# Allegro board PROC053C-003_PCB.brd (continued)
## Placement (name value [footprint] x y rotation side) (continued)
NOREF#226  -  []  106.67 69.55 0 top
NOREF#227  -  []  134.23 67.51 0 top
NOREF#228  -  []  115.71 3.68 90 top
NOREF#229  -  []  169.54 44.35 0 top
NOREF#230  -  []  138.3 47.84 0 top
NOREF#231  -  []  25.4 87.32 90 top
NOREF#232  -  []  139.57 59.14 0 top
NOREF#233  -  []  78.48 33.4 0 top
NOREF#234  -  []  78.48 33.4 90 top
NOREF#235  -  []  65.92 51 90 top
NOREF#236  -  []  8.25 40.97 0 top
NOREF#237  -  []  38.85 125.69 0 top
NOREF#238  -  []  97.04 36.95 90 top
NOREF#239  -  []  90.81 25.78 90 top
NOREF#240  -  []  161.97 70.99 90 top
NOREF#241  -  []  60.57 124.66 90 top
NOREF#242  -  []  103.63 39.76 0 top
NOREF#243  -  []  136.52 67.51 0 top
NOREF#244  -  []  138.04 55.19 90 top
NOREF#245  -  []  97.4 78.94 0 top
NOREF#246  -  []  86.24 67.69 90 top
NOREF#247  -  []  31.49 93.68 0 top
NOREF#248  -  []  28.96 121.23 90 top
NOREF#249  -  []  137.41 132.92 90 top
NOREF#250  -  []  144.01 101.31 0 top
NOREF#251  -  []  143.51 67.51 90 top
NOREF#252  -  []  22.47 134.96 0 top
NOREF#253  -  []  96.24 81.4 0 top
NOREF#254  -  []  78.48 31.24 0 top
NOREF#255  -  []  124.59 28.44 90 top
NOREF#256  -  [unnamed#2]  156.64 72.39 0 top
NOREF#257  -  []  29.6 97.86 90 top
NOREF#258  -  []  92.83 136.36 0 top
NOREF#259  -  []  60.21 63.58 90 top
NOREF#260  -  []  60.7 23.12 0 top
NOREF#261  -  []  28.57 98.39 0 top
NOREF#262  -  []  23.5 133.3 90 top
NOREF#263  -  []  106.9 86.75 0 top
NOREF#264  -  []  141.22 136.48 0 top
NOREF#265  -  []  128.9 30.48 0 top
NOREF#266  -  []  102.15 80.82 90 top
NOREF#267  -  []  120.77 33.9 0 top
NOREF#268  -  []  95.8 76.02 0 top
NOREF#269  -  []  95.88 79.1 0 top
NOREF#270  -  []  90.83 82.5 90 top
NOREF#271  -  []  87.98 82.52 90 top
NOREF#272  -  []  133.84 59.33 90 top
NOREF#273  -  []  95.63 91.02 0 top
NOREF#274  -  []  110.47 86.64 90 top
NOREF#275  -  []  141.6 126.95 0 top
NOREF#276  -  []  161.03 61.05 0 top
NOREF#277  -  []  139.44 130.9 0 top
NOREF#278  -  []  10.79 118.33 0 top
NOREF#279  -  []  25.4 58.37 90 top
NOREF#280  -  []  185.97 62.05 0 top
NOREF#281  -  []  105.53 33.9 0 top
NOREF#282  -  []  106.05 31.87 90 top
NOREF#283  -  []  133.84 44.09 90 top
NOREF#284  -  []  31.49 94.82 90 top
NOREF#285  -  []  58.75 15.21 90 top
NOREF#286  -  []  26.53 50.38 0 top
NOREF#287  -  []  137.29 48.33 90 top
NOREF#288  -  [unnamed#2]  148.59 135.97 0 top
NOREF#289  -  []  93.59 81.4 0 top
NOREF#290  -  []  46.25 103.57 0 top
NOREF#291  -  []  139.95 133.19 0 top
NOREF#292  -  []  76.72 82.88 90 top
NOREF#293  -  []  -15.14 -195.3 0 top
NOREF#294  -  []  75.34 76.65 90 top
NOREF#295  -  []  171.95 23.45 0 top
NOREF#296  -  []  22.34 131.14 90 top
NOREF#297  -  []  138.3 62.56 90 top
NOREF#298  -  []  46.78 103.57 90 top
NOREF#299  -  []  145.92 67.51 0 top
NOREF#300  -  []  175.41 50.28 90 top
NOREF#301  -  []  141.6 58.62 0 top
NOREF#302  -  []  118.87 39.76 0 top
NOREF#303  -  []  154.35 85.09 0 top
NOREF#304  -  []  96.51 32.89 0 top
NOREF#305  -  []  18.28 39.07 90 top
NOREF#306  -  []  111.75 36.95 0 top
NOREF#307  -  []  11.68 31.49 90 top
NOREF#308  -  []  96.4 69.93 90 top
NOREF#309  -  []  90.8 81.27 90 top
NOREF#310  -  []  81.4 81.14 0 top
NOREF#311  -  []  81.8 34.92 90 top
NOREF#312  -  []  160.9 37.54 90 top
NOREF#313  -  []  182.53 98.37 90 top
NOREF#314  -  []  104.79 83.46 0 top
NOREF#315  -  []  103.92 80.82 90 top
NOREF#316  -  []  135.26 52.27 90 top
NOREF#317  -  []  106.16 92.15 90 top
NOREF#318  -  []  170.13 93.43 0 top
NOREF#319  -  []  142.24 60.32 90 top
NOREF#320  -  []  80.77 77.97 0 top
NOREF#321  -  []  103.12 71.45 0 top
NOREF#322  -  []  140.97 132.66 90 top
NOREF#323  -  []  170.93 17.73 0 top
NOREF#324  -  []  29.6 98.88 90 top
NOREF#325  -  []  101.24 73.71 0 top
NOREF#326  -  []  91.71 88.75 90 top
NOREF#327  -  []  174.66 125.68 90 top
NOREF#328  -  []  105.8 137.49 90 top
NOREF#329  -  []  145.92 52.27 0 top
NOREF#330  -  []  157.11 55.58 90 top
NOREF#331  -  []  81.4 82.54 0 top
NOREF#332  -  []  102.88 78.31 90 top
NOREF#333  -  []  108.2 89.32 0 top
NOREF#334  -  []  139.96 67.51 90 top
NOREF#335  -  []  138.56 43.38 90 top
NOREF#336  -  []  154.35 83.96 0 top
NOREF#337  -  []  111.62 27.94 90 top
NOREF#338  -  []  152.65 94.31 90 top
NOREF#339  -  []  114.3 74.81 0 top
NOREF#340  -  []  22.47 133.82 0 top
NOREF#341  -  []  145.04 58.62 90 top
NOREF#342  -  []  104.13 92.15 90 top
NOREF#343  -  []  140.58 52.27 90 top
NOREF#344  -  []  84.71 38.73 90 top
NOREF#345  -  []  48.77 117.55 90 top
NOREF#346  -  []  100.85 78.31 90 top
NOREF#347  -  []  116.96 80.35 0 top
NOREF#348  -  []  24.38 101.44 0 top
NOREF#349  -  []  99.05 80.82 90 top
NOREF#350  -  []  155.92 120.01 90 top
NOREF#351  -  []  101.97 71.45 0 top
NOREF#352  -  []  94.87 125.17 90 top
NOREF#353  -  []  91.71 89.77 0 top
NOREF#354  -  []  100.45 127.45 0 top
NOREF#355  -  []  148.84 70.43 0 top
NOREF#356  -  []  102.15 85.01 90 top
NOREF#357  -  []  172.83 63.58 90 top
NOREF#358  -  []  27.69 31.06 90 top
NOREF#359  -  []  34.15 93.93 90 top
NOREF#360  -  []  34.29 36.39 0 top
NOREF#361  -  []  96.89 126.96 0 top
NOREF#362  -  []  97.28 6.36 0 top
NOREF#363  -  []  104.39 76.94 0 top
NOREF#364  -  []  170.13 92.41 90 top
NOREF#365  -  []  74.32 76.65 0 top
NOREF#366  -  []  98.23 83.17 90 top
NOREF#367  -  []  96.51 36.95 0 top
NOREF#368  -  []  137.55 67.51 90 top
NOREF#369  -  []  29.6 81.1 90 top
NOREF#370  -  []  59.43 40 0 top
NOREF#371  -  []  48.38 24.13 90 top
NOREF#372  -  []  111.75 34.92 0 top
NOREF#373  -  []  23.12 118.94 90 top
NOREF#374  -  []  100.32 78.31 0 top
NOREF#375  -  []  15.24 68.4 90 top
NOREF#376  -  [unnamed#2]  51.46 125.66 0 top
NOREF#377  -  []  80.77 78.99 0 top
NOREF#378  -  []  113.16 137.36 90 top
NOREF#379  -  []  24.91 114.83 0 top
NOREF#380  -  []  175.41 55.36 0 top
NOREF#381  -  []  175.41 50.28 0 top
NOREF#382  -  []  149.61 92.66 90 top
NOREF#383  -  []  31.76 31.06 90 top
NOREF#384  -  []  85.46 36.96 0 top
NOREF#385  -  []  110.48 93.18 0 top
NOREF#386  -  []  25.4 102.05 90 top
NOREF#387  -  []  25.4 84.27 90 top
NOREF#388  -  []  111.62 25.9 0 top
NOREF#389  -  []  29.71 17.41 0 top
NOREF#390  -  []  156.58 55.58 0 top
NOREF#391  -  []  109.35 23.11 90 top
NOREF#392  -  []  105.53 31.87 0 top
NOREF#393  -  []  22.86 117.93 90 top
NOREF#394  -  []  104.13 93.18 0 top
NOREF#395  -  []  169.54 44.35 90 top
NOREF#396  -  []  57.27 37.21 0 top
NOREF#397  -  []  38.85 124.66 90 top
NOREF#398  -  []  108.71 17.52 0 top
NOREF#399  -  []  104.91 76.94 90 top
NOREF#400  -  []  175.4 80.57 90 top
NOREF#401  -  []  96.65 91.51 90 top
NOREF#402  -  []  110.99 31.61 0 top
NOREF#403  -  []  139.69 55.19 0 top
NOREF#404  -  []  90.78 83.87 0 top
NOREF#405  -  []  76.95 115.4 0 top
NOREF#406  -  []  95.75 31.49 0 top
NOREF#407  -  []  173.24 73.86 90 top
NOREF#408  -  []  24.38 60.03 0 top
NOREF#409  -  []  69.22 12.95 90 top
NOREF#410  -  []  101.48 32.38 90 top
NOREF#411  -  []  68.19 12.95 0 top
NOREF#412  -  [unnamed#2]  108.97 42.42 0 top
NOREF#413  -  []  78 55.8 90 top
NOREF#414  -  []  92.83 135.33 90 top
NOREF#415  -  []  25.52 99.26 90 top
NOREF#416  -  []  90.29 85.59 90 top
NOREF#417  -  []  93.72 33.4 0 top
NOREF#418  -  []  18.28 40.09 0 top
NOREF#419  -  []  120.26 137.36 0 top
NOREF#420  -  []  22.74 138.38 90 top
NOREF#421  -  []  80.77 78.99 90 top
NOREF#422  -  []  102.68 82.91 90 top
NOREF#423  -  []  17.66 121.36 90 top
NOREF#424  -  []  138.04 56.22 0 top
NOREF#425  -  []  128.91 23.74 90 top
NOREF#426  -  []  109.44 86.02 0 top
NOREF#427  -  []  139.57 58.62 90 top
NOREF#428  -  []  144.26 122.42 0 top
NOREF#429  -  []  0 0 0 top
NOREF#430  -  []  96.65 90.5 90 top
NOREF#431  -  []  33.78 40.09 0 top
NOREF#432  -  []  105.28 88.85 90 top
NOREF#433  -  []  105.53 28.32 90 top
NOREF#434  -  []  163.95 40.25 0 top
NOREF#435  -  []  175.41 40.12 0 top
NOREF#436  -  []  150.49 57.86 90 top
NOREF#437  -  []  59.94 99.02 0 top
NOREF#438  -  []  139.69 70.43 0 top
NOREF#439  -  []  40.76 121.48 0 top
NOREF#440  -  []  173.54 80.64 90 top
NOREF#441  -  []  75.34 75.64 90 top
NOREF#442  -  []  90.54 72.26 90 top
NOREF#443  -  []  9.28 40.97 90 top
NOREF#444  -  []  100.09 81.85 0 top
NOREF#445  -  []  173.54 78.1 90 top
NOREF#446  -  []  114.17 39.25 0 top
NOREF#447  -  []  25.52 57.24 0 top
NOREF#448  -  [unnamed#3]  185.42 147.32 0 top
NOREF#449  -  []  96.67 88.61 90 top
NOREF#450  -  []  129.04 29.07 90 top
NOREF#451  -  []  36.31 22.86 0 top
NOREF#452  -  []  120.77 25.78 0 top
NOREF#453  -  []  179.32 54.43 90 top
NOREF#454  -  []  29.6 55.32 90 top
NOREF#455  -  []  109.83 77.72 90 top
NOREF#456  -  []  144.01 100.78 90 top
NOREF#457  -  []  186.71 96.47 90 top
NOREF#458  -  []  87.96 83.82 0 top
NOREF#459  -  []  53.71 24.13 90 top
NOREF#460  -  []  146.05 58.62 0 top
NOREF#461  -  []  102.15 82.91 0 top
NOREF#462  -  []  122.42 19.93 0 top
NOREF#463  -  [unnamed#2]  27.56 61.8 0 top
NOREF#464  -  []  100.98 86.31 90 top
NOREF#465  -  []  149.47 97.49 0 top
NOREF#466  -  []  93.72 31.24 90 top
NOREF#467  -  []  37.61 100.17 90 top
NOREF#468  -  []  140.58 52.79 0 top
NOREF#469  -  []  100.45 128.47 0 top
NOREF#470  -  []  142.24 60.84 0 top
NOREF#471  -  []  90.29 31.87 90 top
NOREF#472  -  []  85.21 34.17 0 top
NOREF#473  -  [unnamed#2]  36.2 75.65 0 top
NOREF#474  -  []  175.41 45.2 90 top
NOREF#475  -  []  94.76 77.62 90 top
NOREF#476  -  []  94.81 71.1 0 top
NOREF#477  -  []  97.91 86.28 90 top
NOREF#478  -  []  25.4 105.1 90 top
NOREF#479  -  []  97.37 76.02 90 top
NOREF#480  -  []  -29.48 8.76 90 top
NOREF#481  -  []  135.12 58.62 90 top
NOREF#482  -  []  143.51 52.27 90 top
NOREF#483  -  []  88.13 81.4 90 top
NOREF#484  -  []  94.76 78.65 0 top
NOREF#485  -  []  102.8 73.71 90 top
NOREF#486  -  []  101.48 130.5 90 top
NOREF#487  -  []  93.72 33.4 90 top
NOREF#488  -  []  37.61 100.17 0 top
NOREF#489  -  []  103.39 80.82 0 top
NOREF#490  -  []  56.13 94.95 0 top
NOREF#491  -  []  20.7 120.09 90 top
NOREF#492  -  []  60.57 125.69 0 top
NOREF#493  -  []  112.15 25.9 90 top
NOREF#494  -  []  147.07 58.62 90 top
NOREF#495  -  []  42.03 91.64 90 top
NOREF#496  -  []  172.71 74.89 0 top
NOREF#497  -  []  132.46 127.1 90 top
NOREF#498  -  []  182.52 17.4 0 top
NOREF#499  -  []  28.57 56.86 0 top
NOREF#500  -  []  106.77 76.28 0 top
NOREF#501  -  []  100.33 83.18 90 top
NOREF#502  -  []  102.5 71.45 90 top
NOREF#503  -  []  47.75 118.07 0 top
NOREF#504  -  []  102.15 86.04 0 top
NOREF#505  -  []  81.4 81.14 90 top
NOREF#506  -  []  44.57 141.94 0 top
NOREF#507  -  []  150.49 67 90 top
NOREF#508  -  []  66.67 40 90 top
NOREF#509  -  []  150.49 58.38 0 top
NOREF#510  -  []  167.68 70.99 0 top
NOREF#511  -  []  109.47 84.97 0 top
NOREF#512  -  []  90.78 83.87 90 top
NOREF#513  -  []  31.49 77.04 0 top
NOREF#514  -  []  109.72 72.4 0 top
NOREF#515  -  []  103.64 71.45 90 top
NOREF#516  -  []  105.16 70.94 90 top
NOREF#517  -  []  90.83 82.5 0 top
NOREF#518  -  []  137.54 43.38 0 top
NOREF#519  -  []  97.22 38.88 0 top
NOREF#520  -  []  101.34 78.31 0 top
NOREF#521  -  [unnamed#3]  185.42 5.08 0 top
NOREF#522  -  []  109.44 87.16 0 top
NOREF#523  -  [unnamed#2]  78.74 41.78 0 top
NOREF#524  -  []  105.41 72.97 0 top
NOREF#525  -  []  98.65 73.71 90 top
NOREF#526  -  []  38.87 108.41 90 top
NOREF#527  -  []  24.38 84.8 0 top
NOREF#528  -  []  104.66 73.74 90 top
NOREF#529  -  [unnamed#2]  181.25 143.85 0 top
NOREF#530  -  []  81.27 32.89 0 top
NOREF#531  -  []  134.99 47.57 90 top
NOREF#532  -  []  29.6 80.08 90 top
NOREF#533  -  []  116.2 32.38 0 top
NOREF#534  -  []  135.25 63.57 90 top
NOREF#535  -  []  93.01 72.69 90 top
NOREF#536  -  []  108.53 80.3 0 top
NOREF#537  -  []  58.75 15.74 0 top
NOREF#538  -  []  147.06 96.21 0 top
NOREF#539  -  []  40.89 120.35 0 top
NOREF#540  -  []  155.95 75.53 0 top
NOREF#541  -  []  93.09 28.69 0 top
NOREF#542  -  []  90.29 33.9 0 top
NOREF#543  -  []  103.12 88.72 90 top
NOREF#544  -  []  97.42 125.93 90 top
NOREF#545  -  []  109.35 28.44 90 top
NOREF#546  -  []  46.25 102.56 0 top
NOREF#547  -  []  171.44 68.16 0 top
NOREF#548  -  []  78.48 31.24 90 top
NOREF#549  -  []  139.57 43.9 0 top
NOREF#550  -  []  98.69 72.51 0 top
NOREF#551  -  []  163.2 40.25 90 top
NOREF#552  -  []  154.87 82.93 90 top
NOREF#553  -  []  66.67 76.03 0 top
NOREF#554  -  []  186.49 62.05 90 top
NOREF#555  -  []  102.1 89.75 0 top
NOREF#556  -  []  166.92 88.27 90 top
NOREF#557  -  []  110.48 92.15 90 top
NOREF#558  -  [unnamed#2]  27.69 104.35 0 top
NOREF#559  -  []  96.67 89.64 0 top
NOREF#560  -  []  60.44 40 90 top
NOREF#561  -  []  117.99 78.81 90 top
NOREF#562  -  []  93.85 79.49 90 top
NOREF#563  -  []  140.07 135.46 0 top
NOREF#564  -  []  24.38 87.85 0 top
NOREF#565  -  []  111.89 75.61 90 top
NOREF#566  -  []  44.06 135.85 0 top
NOREF#567  -  []  90.29 28.32 90 top
NOREF#568  -  []  149.36 70.43 90 top
NOREF#569  -  []  98.42 124.67 0 top
NOREF#570  -  []  167.94 89.29 0 top
NOREF#571  -  []  99.95 38.73 90 top
NOREF#572  -  []  175.41 47.74 90 top
NOREF#573  -  []  106.05 33.9 90 top
NOREF#574  -  []  96.33 76.02 90 top
NOREF#575  -  []  174.4 5.21 90 top
NOREF#576  -  []  135.26 67.51 90 top
NOREF#577  -  []  143.51 68.03 0 top
NOREF#578  -  []  101.46 67.39 0 top
NOREF#579  -  []  53.97 94.95 0 top
NOREF#580  -  []  95.75 31.49 90 top
NOREF#581  -  []  107.93 86.23 90 top
NOREF#582  -  []  96.24 81.4 90 top
NOREF#583  -  []  94.11 28.69 90 top
NOREF#584  -  []  80.77 77.97 90 top
NOREF#585  -  []  143.51 52.79 0 top
NOREF#586  -  []  174.13 126.7 0 top
NOREF#587  -  []  28.44 121.23 0 top
NOREF#588  -  []  23.87 35.78 0 top
NOREF#589  -  []  67.19 75.01 90 top
NOREF#590  -  []  18.79 72.48 0 top
NOREF#591  -  []  95.88 78.08 90 top
NOREF#592  -  []  116.72 32.38 90 top
NOREF#593  -  []  142.25 70.43 90 top
NOREF#594  -  []  64.89 51 0 top
NOREF#595  -  []  105.53 29.34 0 top
NOREF#596  -  []  140.71 130.76 0 top
NOREF#597  -  []  81.98 38.88 0 top
NOREF#598  -  [unnamed#2]  36.96 51.26 0 top
NOREF#599  -  [unnamed#2]  93.6 22.61 0 top
NOREF#600  -  []  135.12 59.14 0 top
NOREF#601  -  []  98.01 80.7 0 top
NOREF#602  -  []  133.47 45.03 0 top
NOREF#603  -  []  102.15 81.85 0 top
NOREF#604  -  []  98.12 73.71 0 top
NOREF#605  -  []  98.94 123.65 90 top
NOREF#606  -  []  22.86 118.45 0 top
NOREF#607  -  []  103.45 86.03 0 top
NOREF#608  -  []  17.65 138.38 0 top
NOREF#609  -  []  105.28 87.83 90 top
NOREF#610  -  []  104.26 12.57 0 top
NOREF#611  -  []  104.77 137.49 0 top
NOREF#612  -  []  63.5 121.36 90 top
NOREF#613  -  []  150.49 68.54 0 top
NOREF#614  -  []  60.06 108.41 0 top
NOREF#615  -  []  101.53 76.7 90 top
NOREF#616  -  [unnamed#3]  5.08 5.08 0 top
NOREF#617  -  []  93.09 73.96 0 top
NOREF#618  -  []  102.61 67.39 0 top
NOREF#619  -  []  161.97 70.99 0 top
NOREF#620  -  []  190.5 0 90 top
NOREF#621  -  []  49.65 121.99 90 top
NOREF#622  -  []  24.38 63.08 0 top
NOREF#623  -  []  24.38 105.63 0 top
NOREF#624  -  []  11.68 32.52 0 top
NOREF#625  -  []  115.32 75.3 90 top
NOREF#626  -  []  101.48 129.49 90 top
NOREF#627  -  []  147.06 97.23 0 top
NOREF#628  -  []  44.06 134.82 90 top
NOREF#629  -  []  149.09 93.68 0 top
NOREF#630  -  []  175.41 42.66 0 top
NOREF#631  -  []  76.19 80.85 0 top
NOREF#632  -  []  137.55 52.27 90 top
NOREF#633  -  []  96.84 76.02 0 top
NOREF#634  -  []  15.24 93.16 0 top
NOREF#635  -  []  155.74 102.96 0 top
NOREF#636  -  []  162.68 40.25 0 top
NOREF#637  -  []  152.19 28.25 0 top
NOREF#638  -  []  107.1 89.32 0 top
NOREF#639  -  [unnamed#2]  174.16 14.76 90 top
NOREF#640  -  []  95.33 71.1 90 top
NOREF#641  -  []  135.12 43.9 0 top
NOREF#642  -  []  48.87 91.51 0 top
NOREF#643  -  []  139.57 43.38 90 top
NOREF#644  -  []  116.96 79.34 0 top
NOREF#645  -  []  34.79 77.04 0 top
NOREF#646  -  []  156.98 75 90 top
NOREF#647  -  []  31.49 52.27 0 top
NOREF#648  -  [unnamed#2]  35.94 95.97 0 top
NOREF#649  -  []  96.51 28.19 90 top
NOREF#650  -  []  165.78 79.24 90 top
NOREF#651  -  []  136.5 129.13 0 top
NOREF#652  -  []  174.87 80.57 0 top
NOREF#653  -  []  106.03 76.99 90 top
NOREF#654  -  []  138.3 48.86 0 top
NOREF#655  -  []  77.99 88.64 90 top
NOREF#656  -  []  129.16 46.6 90 top
NOREF#657  -  []  96.11 86.03 90 top
NOREF#658  -  []  144.79 122.42 90 top
NOREF#659  -  []  99.31 83.7 0 top
NOREF#660  -  []  156.27 102.96 90 top
NOREF#661  -  []  107.1 88.29 90 top
NOREF#662  -  []  11.82 117.8 90 top
NOREF#663  -  []  109.42 83.86 0 top
NOREF#664  -  []  28.57 81.62 0 top
NOREF#665  -  []  98.95 86.28 90 top
NOREF#666  -  []  28.57 55.84 0 top
NOREF#667  -  []  103.45 86.03 90 top
NOREF#668  -  []  90.29 25.78 0 top
NOREF#669  -  []  120.77 28.32 90 top
NOREF#670  -  []  34.8 39.57 90 top
NOREF#671  -  []  25.52 81.48 90 top
NOREF#672  -  []  98.95 87.31 0 top
NOREF#673  -  []  161.22 82.8 90 top
NOREF#674  -  []  109.83 76.7 90 top
NOREF#675  -  []  119.76 82 0 top
NOREF#676  -  []  100.5 77.23 0 top
NOREF#677  -  []  111.75 79.2 0 top
NOREF#678  -  []  88.39 39.76 0 top
NOREF#679  -  []  48.38 24.13 0 top
NOREF#680  -  []  106.16 93.18 0 top
NOREF#681  -  []  77.46 86.44 0 top
NOREF#682  -  []  28.57 99.4 0 top
NOREF#683  -  []  95.63 93.05 0 top
NOREF#684  -  []  155.31 24.98 0 top
NOREF#685  -  []  112.26 21.08 0 top
NOREF#686  -  []  24.38 61.05 0 top
NOREF#687  -  []  85.21 33.14 90 top
NOREF#688  -  []  100.19 73.71 0 top
NOREF#689  -  []  101.11 80.82 90 top
NOREF#690  -  []  171.95 22.43 90 top
NOREF#691  -  []  107.2 69.55 90 top
NOREF#692  -  []  105.41 81.04 0 top
NOREF#693  -  []  34.79 52.27 90 top
NOREF#694  -  []  152.65 94.83 0 top
NOREF#695  -  []  49.65 118.33 0 top
NOREF#696  -  []  102.8 75.74 90 top
NOREF#697  -  []  90.29 29.34 0 top
NOREF#698  -  []  132.46 127.1 0 top
NOREF#699  -  []  167.25 46.65 0 top
NOREF#700  -  []  27.17 31.06 0 top
NOREF#701  -  []  86.22 34.17 0 top
NOREF#702  -  []  95.88 69.93 0 top
NOREF#703  -  []  101.11 81.85 0 top
NOREF#704  -  []  97.4 78.94 90 top
NOREF#705  -  []  15.24 68.4 0 top
NOREF#706  -  []  95.63 92.04 0 top
NOREF#707  -  [unnamed#2]  5.08 10.79 0 top
NOREF#708  -  []  33.78 39.08 0 top
NOREF#709  -  []  31.49 77.04 90 top
NOREF#710  -  []  151.63 97.61 0 top
NOREF#711  -  []  86.22 33.14 90 top
NOREF#712  -  []  88.13 81.4 0 top
NOREF#713  -  []  159.94 89.29 0 top
NOREF#714  -  []  152.82 105.63 0 top
NOREF#715  -  []  90.71 88.72 90 top
NOREF#716  -  []  93.72 31.24 0 top
NOREF#717  -  []  103.89 78.31 90 top
NOREF#718  -  []  25.52 99.78 0 top
NOREF#719  -  []  96.27 73.39 0 top
NOREF#720  -  []  91.69 72.26 90 top
NOREF#721  -  []  121.29 31.87 90 top
NOREF#722  -  []  108.32 92.15 90 top
NOREF#723  -  []  95.7 84.65 90 top
NOREF#724  -  []  66.3 140.67 90 top
NOREF#725  -  []  102.28 75.74 0 top
NOREF#726  -  []  83.69 39.25 0 top
NOREF#727  -  []  69.59 139.14 90 top
NOREF#728  -  []  -17.13 -248.13 90 top
NOREF#729  -  []  99.05 81.85 0 top
NOREF#730  -  []  115.06 73.5 0 top
NOREF#731  -  []  104.13 73.74 0 top
NOREF#732  -  []  128.78 24.5 90 top
NOREF#733  -  []  108.96 31.24 90 top
NOREF#734  -  []  105.53 25.78 0 top
NOREF#735  -  []  93.85 79.49 0 top
NOREF#736  -  []  96.39 128.98 90 top
NOREF#737  -  []  134.99 47.57 0 top
NOREF#738  -  []  25.4 100.91 90 top
NOREF#739  -  []  171.44 67.13 90 top
NOREF#740  -  []  24.38 85.81 0 top
NOREF#741  -  []  105.41 72.97 90 top
NOREF#742  -  []  25.52 82 0 top
NOREF#743  -  []  108.96 31.24 0 top
NOREF#744  -  []  108.33 23.11 0 top
NOREF#745  -  []  139.44 129.87 90 top
NOREF#746  -  []  23.87 35.25 90 top
NOREF#747  -  []  167.25 45.62 90 top
NOREF#748  -  []  36.84 22.86 90 top
NOREF#749  -  []  175.41 40.12 90 top
NOREF#750  -  []  95.7 84.65 0 top
NOREF#751  -  []  177.69 17.4 0 top
NOREF#752  -  []  140.07 135.46 90 top
NOREF#753  -  []  102.23 13.34 0 top
NOREF#754  -  []  45.09 141.94 90 top
NOREF#755  -  []  175.41 57.9 0 top
NOREF#756  -  []  142.63 58.62 90 top
NOREF#757  -  []  4.95 33.03 0 top
NOREF#758  -  []  68.19 106.12 90 top
NOREF#759  -  []  175.41 42.66 90 top
NOREF#760  -  []  142.12 126.95 90 top
NOREF#761  -  []  41.79 121.48 90 top
NOREF#762  -  []  87.96 83.82 90 top
NOREF#763  -  []  105.28 89.86 90 top
NOREF#764  -  []  135.25 64.1 0 top
NOREF#765  -  []  99.72 71.99 90 top
NOREF#766  -  []  165.48 53.29 90 top
NOREF#767  -  []  133.47 60.27 90 top
NOREF#768  -  [unnamed#3]  5.08 147.32 0 top
NOREF#769  -  []  104.26 12.57 90 top
NOREF#770  -  []  23.5 134.44 90 top
NOREF#771  -  []  138.3 47.32 90 top
NOREF#772  -  []  66.67 40 0 top
NOREF#773  -  []  136.5 129.13 90 top
NOREF#774  -  []  81.8 32.89 90 top
NOREF#775  -  []  168.83 81.15 0 top
NOREF#776  -  []  103.13 67.39 90 top
NOREF#777  -  []  17.14 121.36 0 top
NOREF#778  -  []  151.63 97.61 90 top
NOREF#779  -  []  41.41 120.35 90 top
NOREF#780  -  []  110.49 84.45 90 top
NOREF#781  -  []  155.92 120.01 0 top
NOREF#782  -  []  112.46 38.88 0 top
NOREF#783  -  []  148.09 96.21 90 top
NOREF#784  -  []  161.54 50.67 90 top
NOREF#785  -  []  152.65 95.97 0 top
NOREF#786  -  []  102.28 73.71 0 top
NOREF#787  -  []  173.87 5.21 0 top
NOREF#788  -  []  120.77 36.44 90 top
NOREF#789  -  []  160.7 82.8 0 top
NOREF#790  -  []  123.57 28.44 0 top
NOREF#791  -  []  38.35 108.41 0 top
NOREF#792  -  []  31.49 92.66 90 top
NOREF#793  -  []  57.27 37.21 90 top
NOREF#794  -  []  129.42 30.48 90 top
NOREF#795  -  []  137.41 133.94 0 top
NOREF#796  -  []  136.52 52.27 0 top
NOREF#797  -  []  115.32 74.29 90 top
NOREF#798  -  []  105.32 83.46 90 top
NOREF#799  -  []  25.43 114.83 90 top
NOREF#800  -  []  101.11 84.21 0 top
NOREF#801  -  []  96.39 129.5 0 top
NOREF#802  -  []  -17.13 -99.99 0 top
NOREF#803  -  []  77.46 89.67 0 top
NOREF#804  -  []  60.46 100.03 90 top
NOREF#805  -  []  150.38 70.43 90 top
NOREF#806  -  []  101.08 89.75 0 top
NOREF#807  -  []  172.31 63.58 0 top
NOREF#808  -  []  172.71 68.5 0 top
NOREF#809  -  []  60.7 22.6 90 top
NOREF#810  -  []  135.12 43.38 90 top
NOREF#811  -  []  96.38 25.78 0 top
NOREF#812  -  [unnamed#2]  41.1 114.74 0 top
NOREF#813  -  []  24.38 102.58 0 top
NOREF#814  -  []  56.49 43.92 0 top
NOREF#815  -  []  85.72 67.69 0 top
NOREF#816  -  []  157.62 108.97 90 top
NOREF#817  -  []  109.55 79.78 90 top
NOREF#818  -  []  120.77 37.47 0 top
NOREF#819  -  []  170.93 24.85 0 top
NOREF#820  -  []  120.77 31.87 0 top
NOREF#821  -  []  110.44 83.33 90 top
NOREF#822  -  []  175.41 52.82 90 top
NOREF#823  -  []  93.85 125.17 0 top
NOREF#824  -  []  24.38 103.59 0 top
NOREF#825  -  []  97.28 5.83 90 top
NOREF#826  -  []  25.4 59.51 90 top
NOREF#827  -  []  97.2 83.69 0 top
NOREF#828  -  []  137.54 58.62 0 top
NOREF#829  -  []  102.23 12.31 90 top
NOREF#830  -  []  24.26 122.88 90 top
NOREF#831  -  []  93.85 128.98 90 top
NOREF#832  -  []  142.24 123.77 0 top
NOREF#833  -  []  119.89 39.23 90 top
NOREF#834  -  []  65.65 40 90 top
NOREF#835  -  []  76.95 114.38 90 top
NOREF#836  -  []  24.38 83.66 0 top
NOREF#837  -  []  106.8 83.36 0 top
NOREF#838  -  []  156.58 57.86 90 top
NOREF#839  -  []  105.41 73.99 0 top
NOREF#840  -  []  96.51 29.21 0 top
NOREF#841  -  []  101.99 67.39 90 top
NOREF#842  -  [unnamed#2]  87.38 66.88 0 top
NOREF#843  -  []  53.71 89.01 90 top
NOREF#844  -  []  101.86 78.31 90 top
NOREF#845  -  []  100.96 32.38 0 top
NOREF#846  -  []  175.41 57.9 90 top
NOREF#847  -  []  105.53 36.44 90 top
NOREF#848  -  []  97.91 87.31 0 top
NOREF#849  -  []  42.03 91.64 0 top
NOREF#850  -  []  63.13 120.35 90 top
NOREF#851  -  []  108.77 78.74 90 top
NOREF#852  -  []  90.71 89.75 0 top
NOREF#853  -  []  107.32 83.36 90 top
NOREF#854  -  []  108.96 33.4 90 top
NOREF#855  -  []  165.48 53.29 0 top
NOREF#856  -  []  136.27 48.33 0 top
NOREF#857  -  []  59.68 63.58 0 top
NOREF#858  -  []  107.74 79.26 0 top
NOREF#859  -  []  112.28 36.95 90 top
NOREF#860  -  []  112.77 78.68 90 top
NOREF#861  -  []  59.94 97.99 90 top
NOREF#862  -  []  110.47 85.49 90 top
NOREF#863  -  []  160.61 79.89 0 top
NOREF#864  -  []  128.01 27.19 0 top
NOREF#865  -  []  152.62 113.97 0 top
NOREF#866  -  []  57.12 89.05 90 top
NOREF#867  -  []  77.46 86.44 90 top
NOREF#868  -  []  140.22 70.43 90 top
NOREF#869  -  []  102.1 88.72 90 top
NOREF#870  -  [unnamed#2]  184.18 8.89 0 top
NOREF#871  -  []  175.41 55.36 90 top
NOREF#872  -  []  140.71 56.22 0 top
NOREF#873  -  [unnamed#2]  27.94 86.82 0 top
NOREF#874  -  []  41.14 101.05 0 top
NOREF#875  -  []  144.01 58.62 0 top
NOREF#876  -  []  156.58 58.89 0 top
NOREF#877  -  []  101.76 73.71 90 top
NOREF#878  -  []  155.11 78.63 0 top
NOREF#879  -  []  90.29 37.47 0 top
NOREF#880  -  []  29.6 56.33 90 top
NOREF#881  -  []  107.93 85.19 90 top
NOREF#882  -  []  128.01 29.6 0 top
NOREF#883  -  []  105.41 73.99 90 top
NOREF#884  -  []  15.24 93.16 90 top
NOREF#885  -  []  108.2 88.29 90 top
NOREF#886  -  []  162.04 37.54 90 top
NOREF#887  -  []  140.71 70.43 90 top
NOREF#888  -  []  97.82 148.45 0 top
NOREF#889  -  []  35.31 36.39 90 top
NOREF#890  -  []  60.44 40 0 top
NOREF#891  -  []  94.1 85.56 0 top
NOREF#892  -  []  56.65 94.95 90 top
NOREF#893  -  []  106.43 80.51 90 top
NOREF#894  -  []  170.93 23.83 90 top
NOREF#895  -  []  53.71 24.13 0 top
NOREF#896  -  []  121.29 25.78 90 top
NOREF#897  -  []  98.43 77.82 90 top
NOREF#898  -  []  120.77 29.34 0 top
NOREF#899  -  []  37.33 22.86 0 top
NOREF#900  -  []  179.32 54.43 0 top
NOREF#901  -  []  31.23 31.06 0 top
NOREF#902  -  [unnamed#2]  117.22 96.98 0 top
NOREF#903  -  []  150.11 100.78 0 top
NOREF#904  -  []  108.32 93.18 0 top
NOREF#905  -  []  138.93 67.51 0 top
NOREF#906  -  [unnamed#2]  130.94 70.69 0 bottom
NOREF#907  -  [unnamed#2]  156.84 89.49 0 bottom
NOREF#908  -  [unnamed#2]  131.06 40.72 0 bottom
NOREF#909  -  [unnamed#2]  181.25 143.85 180 bottom
NOREF#910  -  [unnamed#2]  4.45 142.96 180 bottom
NOREF#911  -  [unnamed#2]  86.49 118.06 180 bottom
NOREF#912  -  [unnamed#2]  33.66 32.59 270 bottom
NOREF#913  -  [unnamed#2]  188.09 63.33 0 bottom
NOREF#914  -  [unnamed#2]  26.16 123.02 270 bottom
NOREF#915  -  [unnamed#2]  104.77 135.21 180 bottom
NOREF#916  -  [unnamed#2]  151.89 55.71 0 bottom
NOREF#917  -  [unnamed#2]  184.18 8.89 180 bottom
NOREF#918  -  [unnamed#2]  25.91 40.47 270 bottom
NOREF#919  -  [unnamed#2]  5.08 10.79 180 bottom
NOREF#920  -  [unnamed#2]  144.15 102.32 0 bottom
Q1  BSS138  [SOT23-3]  12.45 3.76 90 bottom
Q2  BSS138  [SOT23-3]  19.05 3.76 90 bottom
Q3  BSS138  [SOT23-3]  12.45 10.37 90 bottom
Q4  BSS138  [SOT23-3]  19.05 10.37 90 bottom
Q5  BSS138  [SOT23-3]  12.45 7.07 90 bottom
Q6  BSS138  [SOT23-3]  19.05 7.07 90 bottom
Q7  NTF6P02T3G  [SOT223]  45.59 112.6 0 bottom
Q8  NTF6P02T3G  [SOT223]  67.44 111.84 0 top
Q9  BSS138  [SOT23-3]  74.3 148.54 90 top
Q10  BSS138  [SOT23-3]  12.45 20.53 90 bottom
Q11  BSS138  [SOT23-3]  12.45 13.92 90 bottom
Q12  BSS138  [SOT23-3]  19.05 17.23 90 bottom
Q13  BSS138  [SOT23-3]  19.05 13.92 90 bottom
Q14  BSS138  [SOT23-3]  19.05 20.66 90 bottom
Q15  BSS138  [SOT23-3]  12.45 17.23 90 bottom
Q16  BSS138  [SOT23-3]  143.13 13.84 0 top
Q20  BSS138  [SOT23-3]  79.98 103.22 180 bottom
Q21  BSS138  [SOT23-3]  76.55 103.22 180 bottom
Q22  BSS138  [SOT23-3]  73.12 103.22 180 bottom
Q23  BSS138  [SOT23-3]  69.85 94.06 180 bottom
Q24  BSS138  [SOT23-3]  69.72 86.95 180 bottom
Q25  BSS138  [SOT23-3]  69.34 101.17 180 bottom
Q26  MMBT2907A  [SOT23-3-44M]  38.86 97.16 90 bottom
Q27  MMBT2907A  [SOT23-3-44M]  113.41 128.27 180 bottom
R1_1  0  [SM-7351-RES-0603]  179.31 7.63 90 top
R2  10K  [SM-7351-RES-0402]  127.89 64.85 0 top
R2_1  10K  [SM-7351-RES-0402]  172.7 6.49 180 top
R3  22.1  [SM-7351-RES-0402]  182.02 96.6 0 bottom
R4  1M  [SM-7351-RES-0402]  77.6 82.38 270 top
R5  0  [SM-7351-RES-0402]  79.25 82.76 180 top
R6  0  [SM-7351-RES-0402]  133.73 74.07 0 top
R7  0  [SM-7351-RES-0402]  124.08 65.49 0 top
R8  0  [SM-7351-RES-0402]  124.08 69.3 0 top
R9  0  [SM-7351-RES-0402]  136.91 126.45 180 bottom
R10  10K  [SM-7351-RES-0402]  170.05 45.76 180 bottom
R11  100  [SM-7351-RES-0402]  168.15 53.55 0 bottom
R13  0  [SM-7351-RES-0402]  69.74 82.33 180 top
R14  0  [SM-7351-RES-0402]  130.43 114.76 270 top
R15  0  [SM-7351-RES-0402]  132.72 114.76 270 top
R16  1K  [SM-7351-RES-0402]  134.49 122.38 180 bottom
R17  1K  [SM-7351-RES-0402]  137.13 122.3 180 bottom
R18  10K  [SM-7351-RES-0402]  144.54 126.96 90 bottom
R19  0  [SM-7351-RES-0402]  142.49 140.54 90 top
R20  0  [SM-7351-RES-0402]  142.88 135.97 90 top
R21  1K  [SM-7351-RES-0402]  138.94 128.35 270 bottom
R22  10K  [SM-7351-RES-0402]  89.79 108.79 270 top
R23  0  [SM-7351-RES-0402]  101.85 112.48 270 top
R24  0  [SM-7351-RES-0402]  101.98 99.78 270 top
R25  0  [SM-7351-RES-0402]  98.68 108.79 270 top
R26  0  [SM-7351-RES-0402]  91.06 124.16 90 top
R27  0  [SM-7351-RES-0402]  91.06 108.79 270 top
R28  0  [SM-7351-RES-0402]  101.35 124.16 90 top
R29  0  [SM-7351-RES-0402]  97.41 124.16 90 top
R30  0  [SM-7351-RES-0402]  92.33 124.16 90 top
R31  0  [SM-7351-RES-0402]  101.85 114.51 270 top
R32  10K  [SM-7351-RES-0402]  124.71 40.51 0 top
R33  10K  [SM-7351-RES-0402]  108.84 40.51 180 top
R34  10K  [SM-7351-RES-0402]  124.71 38.48 0 top
R35  10K  [SM-7351-RES-0402]  108.84 39.5 180 top
R36  18.2K  [SM-7351-RES-0402]  124.59 42.75 180 top
R37  10K  [SM-7351-RES-0402]  124.71 39.5 0 top
R38  10K  [SM-7351-RES-0402]  108.84 37.46 180 top
R39  10K  [SM-7351-RES-0402]  124.71 37.46 0 top
R40  10K  [SM-7351-RES-0402]  108.84 38.48 180 top
R41  240  [SM-7351-RES-0402]  93.6 30.1 180 top
R42  240  [SM-7351-RES-0402]  124.08 30.1 180 top
R44  240  [SM-7351-RES-0402]  108.84 30.1 180 top
R45  10K  [SM-7351-RES-0402]  111.12 15.11 0 top
R46  49.9  [SM-7351-RES-0402]  127.51 31.5 180 bottom
R47  49.9  [SM-7351-RES-0402]  127.51 30.48 180 bottom
R48  10K  [SM-7351-RES-0402]  111.12 13.97 180 top
R49  47  [SM-7351-RES-0402]  124.08 29.59 180 bottom
R50  47  [SM-7351-RES-0402]  108.84 26.42 0 top
R51  47  [SM-7351-RES-0402]  108.71 30.35 0 bottom
R52  47  [SM-7351-RES-0402]  108.71 27.81 0 bottom
R53  47  [SM-7351-RES-0402]  117.22 21.72 90 bottom
R54  47  [SM-7351-RES-0402]  118.24 21.72 90 bottom
R55  47  [SM-7351-RES-0402]  119.25 21.72 90 bottom
R56  100K  [SM-7351-RES-0402]  108.2 11 270 top
R57  47  [SM-7351-RES-0402]  116.46 21.72 90 top
R58  47  [SM-7351-RES-0402]  114.17 21.72 90 bottom
R59  47  [SM-7351-RES-0402]  124.08 26.29 180 top
R60  47  [SM-7351-RES-0402]  116.2 21.72 90 bottom
R61  47  [SM-7351-RES-0402]  124.08 25.02 180 bottom
R62  47  [SM-7351-RES-0402]  113.16 21.72 90 top
R63  47  [SM-7351-RES-0402]  120.27 21.72 90 top
R64  47  [SM-7351-RES-0402]  114.17 21.72 90 top
R65  47  [SM-7351-RES-0402]  117.47 21.72 90 top
R66  47  [SM-7351-RES-0402]  124.08 31.88 180 top
R67  0  [SM-7351-RES-0402]  106.3 11.51 180 top
R68  47  [SM-7351-RES-0402]  121.54 21.72 90 bottom
R69  10  [SM-7351-RES-0402]  104.65 17.4 180 top
R70  47  [SM-7351-RES-0402]  115.32 21.72 90 top
R71  47  [SM-7351-RES-0402]  118.49 21.72 90 top
R72  47  [SM-7351-RES-0402]  115.19 21.72 90 bottom
R73  47  [SM-7351-RES-0402]  124.08 27.56 180 top
R74  47  [SM-7351-RES-0402]  120.4 21.72 90 bottom
R75  47  [SM-7351-RES-0402]  108.84 27.56 0 top
R76  2.2K  [SM-7351-RES-0402]  25.91 121.11 0 bottom
R77  0  [SM-7351-RES-0402]  22.48 136.48 90 bottom
R78  0  [SM-7351-RES-0402]  7.75 141.69 180 bottom
R79  DNI  [SM-7351-RES-0402]  38.25 110.75 90 top
R80  DNI  [SM-7351-RES-0402]  32.66 110.75 90 top
R81  DNI  [SM-7351-RES-0402]  35.46 110.75 90 top
R82  DNI  [SM-7351-RES-0402]  36.86 110.75 90 top
R83  0  [SM-7351-RES-0402]  24.77 112.73 270 bottom
R84  DNI  [SM-7351-RES-0402]  34.06 110.75 90 top
R85  DNI  [SM-7351-RES-0402]  31.27 110.75 90 top
R86  0  [SM-7351-RES-0402]  23.68 112.73 270 bottom
R87  DNI  [SM-7351-RES-0402]  87.38 102.19 90 top
R88  DNI  [SM-7351-RES-0402]  86.11 102.19 90 top
R89  0  [SM-7351-RES-0402]  7.24 119.72 180 bottom
R90  DNI  [SM-7351-RES-0402]  91.19 102.19 90 top
R91  DNI  [SM-7351-RES-0402]  89.92 102.19 90 top
R92  DNI  [SM-7351-RES-0402]  84.84 102.19 90 top
R93  0  [SM-7351-RES-0402]  6.48 132.03 270 bottom
R94  DNI  [SM-7351-RES-0402]  88.65 102.19 90 top
R95  DNI  [SM-7351-RES-0402]  22.86 110.7 270 bottom
R96  0  [SM-7351-RES-0402]  25.91 118.83 0 bottom
R97  0  [SM-7351-RES-0603]  23.49 123.78 270 top
R98  0  [SM-7351-RES-0402]  25.91 119.84 0 bottom
R99  49.9  [SM-7351-RES-0402]  17.84 123.53 0 bottom
R100  49.9  [SM-7351-RES-0402]  19.87 123.53 180 bottom
R101  49.9  [SM-7351-RES-0402]  22.61 127.21 90 bottom
R102  49.9  [SM-7351-RES-0402]  22.61 129.24 270 bottom
R103  4.87K  [SM-7351-RES-0402]  23.49 121.11 180 top
R104  2.2K  [SM-7351-RES-0402]  22.03 113.11 90 bottom
R105  DNI  [SM-7351-RES-0402]  86.11 114.13 270 top
R106  0  [SM-7351-RES-0402]  6.48 129.88 90 bottom
R107  10K  [SM-7351-RES-0402]  43.05 86.82 270 bottom
R108  2.2K  [SM-7351-RES-0402]  17.53 115.78 90 bottom
R109  2.2K  [SM-7351-RES-0402]  18.73 114.25 90 bottom
R110  2.2K  [SM-7351-RES-0402]  19.87 114.25 90 bottom
R111  2.2K  [SM-7351-RES-0402]  21.02 114.25 90 bottom
R112  0  [SM-7351-RES-0402]  44.7 87.33 0 bottom
R113  62  [SM-7351-RES-0402]  140.34 14.86 180 top
R114  0  [SM-7351-RES-0402]  141.61 10.41 0 top
R115  0  [SM-7351-RES-0402]  27.05 74.35 90 top
R116  2.2K  [SM-7351-RES-0402]  141.61 11.43 0 top
R117  0  [SM-7351-RES-0402]  29.59 74.35 90 top
R118  0  [SM-7351-RES-0402]  32.13 74.35 90 top
R119  0  [SM-7351-RES-0402]  34.67 74.35 90 top
R120  2.2K  [SM-7351-RES-0402]  29.59 93.17 270 top
R121  0  [SM-7351-RES-0402]  23.37 99.27 270 bottom
R122  0  [SM-7351-RES-0402]  7.7 117.55 180 bottom
R123  DNI  [SM-7351-RES-0402]  114.68 99.78 270 top
R124  DNI  [SM-7351-RES-0402]  118.49 99.9 270 top
R125  DNI  [SM-7351-RES-0402]  114.55 103.84 90 top
R126  DNI  [SM-7351-RES-0402]  119.63 103.84 90 top
R127  DNI  [SM-7351-RES-0402]  116.08 99.78 270 top
R128  DNI  [SM-7351-RES-0402]  117.47 99.9 270 top
R129  DNI  [SM-7351-RES-0402]  118.36 103.84 90 top
R130  DNI  [SM-7351-RES-0402]  117.09 103.84 90 top
R131  2.2K  [SM-7351-RES-0402]  27.69 95.33 270 top
R132  DNI  [SM-7351-RES-0402]  52.58 109.56 90 top
R133  DNI  [SM-7351-RES-0402]  58.17 109.56 90 top
R134  0  [SM-7351-RES-0402]  7.19 95.58 180 bottom
R135  DNI  [SM-7351-RES-0402]  59.56 109.56 90 top
R136  DNI  [SM-7351-RES-0402]  120.9 103.84 90 top
R137  DNI  [SM-7351-RES-0402]  115.82 103.84 90 top
R138  0  [SM-7351-RES-0603]  6.48 108.67 270 bottom
R139  DNI  [SM-7351-RES-0402]  56.77 109.56 90 top
R140  0  [SM-7351-RES-0402]  30.61 95.33 270 top
R141  0  [SM-7351-RES-0603]  29.34 101.55 270 bottom
R142  0  [SM-7351-RES-0402]  29.59 95.33 270 top
R143  49.9  [SM-7351-RES-0402]  24.38 106.89 270 top
R144  49.9  [SM-7351-RES-0402]  24.38 104.86 90 top
R145  49.9  [SM-7351-RES-0402]  24.38 102.82 270 top
R146  49.9  [SM-7351-RES-0402]  24.38 100.67 90 top
R147  4.87K  [SM-7351-RES-0402]  26.03 97.74 0 top
R148  DNI  [SM-7351-RES-0402]  55.37 109.56 90 top
R149  10K  [SM-7351-RES-0402]  186.72 83.14 180 bottom
R150  DNI  [SM-7351-RES-0402]  53.98 109.56 90 top
R151  0  [SM-7351-RES-0402]  6.43 105.74 90 bottom
R152  2.2K  [SM-7351-RES-0402]  37.39 100.16 0 top
R153  10K  [SM-7351-RES-0402]  33.15 89.74 90 bottom
R154  0  [SM-7351-RES-0402]  34.8 89.24 0 bottom
R155  2.2K  [SM-7351-RES-0402]  37.34 104.73 180 top
R156  2.2K  [SM-7351-RES-0402]  37.34 103.59 180 top
R157  2.2K  [SM-7351-RES-0402]  37.34 102.44 180 top
R158  2.2K  [SM-7351-RES-0402]  37.34 101.3 180 top
R159  2.2K  [SM-7351-RES-0402]  28.19 77.55 270 top
R160  0  [SM-7351-RES-0402]  23.37 75.14 270 bottom
R161  0  [SM-7351-RES-0402]  7.75 93.43 180 bottom
R162  0  [SM-7351-RES-0402]  124.08 82.76 180 top
R163  0  [SM-7351-RES-0402]  124.08 81.62 180 top
R164  0  [SM-7351-RES-0402]  124.08 83.9 180 top
R165  0  [SM-7351-RES-0402]  37.34 77.68 0 top
R166  0  [SM-7351-RES-0402]  37.34 78.82 0 top
R167  0  [SM-7351-RES-0402]  120.27 84.54 180 top
R168  0  [SM-7351-RES-0402]  120.27 82.25 180 top
R169  0  [SM-7351-RES-0402]  124.08 85.17 180 top
R170  0  [SM-7351-RES-0402]  37.34 81.11 0 top
R171  0  [SM-7351-RES-0402]  37.34 83.52 0 bottom
R172  0  [SM-7351-RES-0402]  7.24 71.46 180 bottom
R173  0  [SM-7351-RES-0402]  37.34 84.66 0 bottom
R174  0  [SM-7351-RES-0402]  37.34 85.81 0 bottom
R175  0  [SM-7351-RES-0402]  37.34 86.95 0 bottom
R176  0  [SM-7351-RES-0402]  6.48 83.77 270 bottom
R177  0  [SM-7351-RES-0402]  37.34 79.96 0 top
R179  0  [SM-7351-RES-0402]  30.61 77.55 270 top
R180  0  [SM-7351-RES-0603]  29.34 83.77 270 bottom
R181  0  [SM-7351-RES-0402]  29.59 77.55 270 top
R182  49.9  [SM-7351-RES-0402]  24.38 89.11 270 top
R183  49.9  [SM-7351-RES-0402]  24.38 87.08 90 top
R184  49.9  [SM-7351-RES-0402]  24.38 85.04 270 top
R185  49.9  [SM-7351-RES-0402]  24.38 82.89 90 top
R186  4.87K  [SM-7351-RES-0402]  28.19 77.55 90 bottom
R187  2.2K  [SM-7351-RES-0402]  37.34 82.5 180 top
R188  0  [SM-7351-RES-0402]  120.27 78.06 180 top
R189  0  [SM-7351-RES-0402]  6.48 81.62 90 bottom
R190  10K  [SM-7351-RES-0402]  20.19 69.3 90 bottom
R191  2.2K  [SM-7351-RES-0402]  37.34 86.95 180 top
R192  2.2K  [SM-7351-RES-0402]  37.34 85.81 180 top
R193  2.2K  [SM-7351-RES-0402]  37.34 84.66 180 top
R194  2.2K  [SM-7351-RES-0402]  37.34 83.52 180 top
R195  0  [SM-7351-RES-0402]  21.84 68.79 0 bottom
R196  0  [SM-7351-RES-0402]  26.92 68.25 90 top
R197  0  [SM-7351-RES-0402]  29.46 68.25 90 top
R198  0  [SM-7351-RES-0402]  32 68.25 90 top
R199  0  [SM-7351-RES-0402]  34.54 68.25 90 top
R200  2.2K  [SM-7351-RES-0402]  28.19 52.79 270 top
R201  2.2K  [SM-7351-RES-0402]  29.59 50.63 270 top
R202  0  [SM-7351-RES-0402]  23.37 50.37 270 bottom
R203  0  [SM-7351-RES-0402]  7.75 68.66 180 bottom
R204  0  [SM-7351-RES-0402]  78.36 95.97 0 top
R205  0  [SM-7351-RES-0402]  78.36 98 0 top
R206  0  [SM-7351-RES-0402]  78.36 94.95 0 top
R207  0  [SM-7351-RES-0402]  78.36 93.93 0 top
R208  0  [SM-7351-RES-0402]  78.36 92.92 0 top
R209  0  [SM-7351-RES-0402]  37.34 52.91 0 top
R210  0  [SM-7351-RES-0402]  78.36 96.98 0 top
R211  0  [SM-7351-RES-0402]  37.34 54.06 0 top
R212  0  [SM-7351-RES-0402]  37.34 56.34 0 top
R213  0  [SM-7351-RES-0402]  37.34 58.76 0 bottom
R214  0  [SM-7351-RES-0402]  7.24 46.69 180 bottom
R215  0  [SM-7351-RES-0402]  37.34 59.9 0 bottom
R216  0  [SM-7351-RES-0402]  37.34 61.04 0 bottom
R217  0  [SM-7351-RES-0402]  37.34 62.18 0 bottom
R218  0  [SM-7351-RES-0603]  6.48 59.39 270 bottom
R219  0  [SM-7351-RES-0402]  37.34 55.2 0 top
R220  DNI  [SM-7351-RES-0402]  124.08 74.76 180 top
R221  0  [SM-7351-RES-0402]  30.61 52.79 270 top
R222  0  [SM-7351-RES-0603]  29.34 59.01 270 bottom
R223  0  [SM-7351-RES-0402]  29.59 52.79 270 top
R224  49.9  [SM-7351-RES-0402]  24.38 64.34 270 top
R225  49.9  [SM-7351-RES-0402]  24.38 62.31 90 top
R226  49.9  [SM-7351-RES-0402]  24.38 60.28 270 top
R227  49.9  [SM-7351-RES-0402]  24.38 58.12 90 top
R228  4.87K  [SM-7351-RES-0402]  28.19 52.79 90 bottom
R230  0  [SM-7351-RES-0402]  124.08 77.17 180 top
R231  0  [SM-7351-RES-0402]  6.48 56.6 270 bottom
R232  2.2K  [SM-7351-RES-0402]  37.34 57.74 0 bottom
R233  10K  [SM-7351-RES-0402]  28.19 46.44 90 bottom
R234  0  [SM-7351-RES-0402]  29.84 45.93 0 bottom
R235  2.2K  [SM-7351-RES-0402]  37.34 62.18 180 top
R236  2.2K  [SM-7351-RES-0402]  37.34 61.04 180 top
R237  2.2K  [SM-7351-RES-0402]  37.34 59.9 180 top
R238  2.2K  [SM-7351-RES-0402]  37.34 58.76 180 top
R239  220  [SM-7351-RES-0402]  9.53 4.7 180 bottom
R240  220  [SM-7351-RES-0402]  16.13 4.7 180 bottom
R241  0  [SM-7351-RES-0402]  9.53 3.64 180 bottom
R242  220  [SM-7351-RES-0402]  9.53 11.43 180 bottom
R243  0  [SM-7351-RES-0402]  16.13 3.64 180 bottom
R244  220  [SM-7351-RES-0402]  16.13 11.43 180 bottom
R245  100K  [SM-7351-RES-0402]  9.53 2.62 0 bottom
R246  100K  [SM-7351-RES-0402]  16.13 2.62 0 bottom
R247  0  [SM-7351-RES-0402]  9.53 10.37 0 bottom
R248  0  [SM-7351-RES-0402]  16.13 10.37 0 bottom
R249  220  [SM-7351-RES-0402]  9.53 8 180 bottom
R250  220  [SM-7351-RES-0402]  16.13 8 180 bottom
R251  100K  [SM-7351-RES-0402]  9.53 9.35 0 bottom
R252  100K  [SM-7351-RES-0402]  16.13 9.35 0 bottom
R253  0  [SM-7351-RES-0402]  9.53 6.94 0 bottom
R254  0  [SM-7351-RES-0402]  16.13 6.94 0 bottom
R255  100K  [SM-7351-RES-0402]  9.53 5.92 0 bottom
R256  100K  [SM-7351-RES-0402]  16.13 5.92 0 bottom
R257  0  [SM-7351-RES-0402]  159 142.83 270 top
R258  0  [SM-7351-RES-0402]  162.71 133.56 90 top
R259  10K  [SM-7351-RES-0402]  177.95 133.56 270 bottom
R260  0  [SM-7351-RES-0402]  161.54 142.83 90 top
R261  0  [SM-7351-RES-0402]  164.11 133.56 270 top
R262  0  [SM-7351-RES-0402]  165.38 133.56 90 top
R263  0  [SM-7351-RES-0402]  166.65 133.56 270 top
R264  0  [SM-7351-RES-0402]  167.79 133.56 90 top
R265  0  [SM-7351-RES-0402]  169.19 133.56 270 top
R267  0  [SM-7351-RES-0402]  174.27 133.56 270 top
R269  0  [SM-7351-RES-0402]  176.81 133.56 270 top
R271  0  [SM-7351-RES-0402]  179.35 133.56 270 top
R273  0  [SM-7351-RES-0402]  181.89 133.56 270 top
R274  0  [SM-7351-RES-0402]  180.62 133.56 90 top
R275  0  [SM-7351-RES-0402]  185.57 133.56 90 top
R276  22.1  [SM-7351-RES-0402]  163.83 144.02 0 bottom
R277  0  [SM-7351-RES-0402]  188.11 133.56 90 top
R278  0  [SM-7351-RES-0603]  29.29 115.5 270 bottom
R279  1.5K OHM  [RC0402]  41.15 116.36 180 top
R280  100K  [SM-7351-RES-0402]  38.99 110.7 0 bottom
R281  22.1  [SM-7351-RES-0402]  84.84 103.21 270 top
R282  22.1  [SM-7351-RES-0402]  86.11 103.21 270 top
R283  22.1  [SM-7351-RES-0402]  87.38 103.21 270 top
R284  22.1  [SM-7351-RES-0402]  88.65 103.21 270 top
R285  22.1  [SM-7351-RES-0402]  36.86 111.76 270 top
R286  22.1  [SM-7351-RES-0402]  89.92 103.21 270 top
R287  22.1  [SM-7351-RES-0402]  91.19 103.21 270 top
R288  22.1  [SM-7351-RES-0402]  38.25 111.76 270 top
R289  22.1  [SM-7351-RES-0402]  35.46 111.76 270 top
R290  22.1  [SM-7351-RES-0402]  34.06 111.76 270 top
R291  22.1  [SM-7351-RES-0402]  32.66 111.76 270 top
R292  22.1  [SM-7351-RES-0402]  31.27 111.76 270 top
R293  220  [SM-7351-RES-0402]  33.02 145.37 90 bottom
R294  0  [SM-7351-RES-0402]  39.55 113.95 270 top
R295  0  [SM-7351-RES-0402]  41.15 117.43 0 top
R296  220  [SM-7351-RES-0402]  34.16 145.37 90 bottom
R297  4.7K  [SM-7351-RES-0402]  41.15 118.45 0 top
R298  12.1K  [SM-7351-RES-0402]  41.15 124.54 0 top
R299  10K  [SM-7351-RES-0402]  35.48 113.95 270 top
R300  DNI  [SM-7351-RES-0402]  163.83 145.29 0 bottom
R301  10K  [SM-7351-RES-0402]  34.09 113.95 270 top
R304  1K  [SM-7351-RES-0402]  36.88 113.95 270 top
R305  1M  [SM-7351-RES-0402]  45.5 103.06 270 bottom
R306  10K  [SM-7351-RES-0402]  32.77 114 270 top
R308  0  [SM-7351-RES-0402]  45.5 105.1 270 bottom
R309  10K  [SM-7351-RES-0402]  31.5 114 270 top
R310  33  [SM-7351-RES-0402]  38 103.95 180 bottom
R312  0  [SM-7351-RES-0402]  43.81 103.59 270 top
R313  33  [SM-7351-RES-0402]  38 105.1 180 bottom
R314  0  [SM-7351-RES-0402]  42.8 103.59 270 top
R315  33  [SM-7351-RES-0402]  38 107 180 bottom
R317  1K  [SM-7351-RES-0402]  38.28 113.95 270 top
R319  1K  [SM-7351-RES-0402]  28.45 124.03 0 top
R321  1K  [SM-7351-RES-0402]  28.45 121.11 0 top
R322  0  [SM-7351-RES-0603]  50.67 112.22 270 bottom
R324  100K  [SM-7351-RES-0402]  60.71 110.7 0 bottom
R325  22.1  [SM-7351-RES-0402]  119.63 104.86 270 top
R326  22.1  [SM-7351-RES-0402]  114.55 104.86 270 top
R327  22.1  [SM-7351-RES-0402]  117.09 104.86 270 top
R328  22.1  [SM-7351-RES-0402]  59.56 110.57 270 top
R329  22.1  [SM-7351-RES-0402]  58.17 110.57 270 top
R330  22.1  [SM-7351-RES-0402]  120.9 104.86 270 top
R331  22.1  [SM-7351-RES-0402]  115.82 104.86 270 top
R332  22.1  [SM-7351-RES-0402]  118.36 104.86 270 top
R333  22.1  [SM-7351-RES-0402]  56.77 110.57 270 top
R334  22.1  [SM-7351-RES-0402]  55.37 110.57 270 top
R335  22.1  [SM-7351-RES-0402]  53.98 110.57 270 top
R336  22.1  [SM-7351-RES-0402]  52.58 110.57 270 top
R337  220  [SM-7351-RES-0402]  54.74 145.37 90 bottom
R338  0  [SM-7351-RES-0402]  60.83 112.98 270 top
R339  0  [SM-7351-RES-0402]  62.99 117.05 0 top
R340  220  [SM-7351-RES-0402]  55.88 145.37 90 bottom
R341  12.1K  [SM-7351-RES-0402]  61.72 125.18 90 top
R342  4.7K  [SM-7351-RES-0402]  62.99 118.45 0 top
R343  10K  [SM-7351-RES-0402]  56.77 112.98 270 top
R345  10K  [SM-7351-RES-0402]  55.37 112.98 270 top
R348  1K  [SM-7351-RES-0402]  58.17 112.98 270 top
R349  1M  [SM-7351-RES-0402]  59.18 99.52 270 bottom
R351  0  [SM-7351-RES-0402]  59.18 101.68 270 bottom
R352  10K  [SM-7351-RES-0402]  53.98 112.98 270 top
R353  10K  [SM-7351-RES-0402]  52.58 112.98 270 top
R354  33  [SM-7351-RES-0402]  52.07 96.09 270 bottom
R356  DNI  [SM-7351-RES-0402]  57.78 106.13 90 bottom
R357  33  [SM-7351-RES-0402]  50.8 96.09 270 bottom
R358  DNI  [SM-7351-RES-0402]  56.64 106.13 90 bottom
R359  33  [SM-7351-RES-0402]  53.21 106.13 90 bottom
R361  1K  [SM-7351-RES-0402]  59.56 112.98 270 top
R363  1K  [SM-7351-RES-0402]  50.16 124.03 0 top
R364  10K  [SM-7351-RES-0402]  50.16 120.48 0 top
R366  10K  [SM-7351-RES-0402]  178.31 54.95 270 top
R367  0  [SM-7351-RES-0402]  127.89 75.27 180 top
R368  1.2K  [SM-7351-CAP-0805]  178.97 58.17 0 bottom
R369  0  [SM-7351-RES-0402]  127.89 76.28 180 top
R370  1.2K  [SM-7351-CAP-0805]  178.97 55.63 0 bottom
R371  0  [SM-7351-RES-0402]  85.47 94.36 0 top
R372  1.2K  [SM-7351-CAP-0805]  178.97 53.09 0 bottom
R373  1.2K  [SM-7351-CAP-0805]  178.97 48.01 0 bottom
R374  1.2K  [SM-7351-CAP-0805]  178.97 50.55 0 bottom
R375  1.2K  [SM-7351-CAP-0805]  178.97 45.47 0 bottom
R376  1.2K  [SM-7351-CAP-0805]  178.97 42.93 0 bottom
R377  0  [SM-7351-RES-0402]  121.54 71.33 180 top
R378  1.2K  [SM-7351-CAP-0805]  178.98 40.39 0 bottom
R379  49.9  [SM-7351-CAP-0805]  185.29 75.01 270 bottom
R380  0  [SM-7351-RES-0402]  177.29 74.12 270 bottom
R381  0  [SM-7351-RES-0402]  178.69 74.12 270 bottom
R382  25K  [SM-7351-RES-0603]  182.37 73.87 0 bottom
R383  2.2K  [SM-7351-RES-0402]  127.89 69.3 0 top
R384  2.2K  [SM-7351-RES-0402]  127.89 72.47 0 top
R385  0  [SM-7351-RES-0402]  127.89 71.46 180 top
R386  150  [SM-7351-RES-0402]  176.15 37.46 0 top
R387  0  [SM-7351-RES-0402]  127.89 70.31 180 top
R388  150  [SM-7351-RES-0402]  176.15 35.31 0 top
R389  150  [SM-7351-RES-0402]  176.15 33.15 0 top
R390  150  [SM-7351-RES-0402]  176.15 30.99 0 top
R391  150  [SM-7351-RES-0402]  176.15 28.83 0 top
R392  150  [SM-7351-RES-0402]  176.15 26.67 0 top
R393  0  [SM-7351-RES-0402]  124.08 72.34 0 top
R394  0  [SM-7351-RES-0402]  124.08 70.69 0 top
R395  150  [SM-7351-RES-0402]  176.15 24.51 0 top
R396  150  [SM-7351-RES-0402]  176.15 22.35 0 top
R397  10K  [SM-7351-RES-0402]  95.25 148.37 180 bottom
R398  10K  [SM-7351-RES-0402]  95.25 149.39 180 bottom
R399  10K  [SM-7351-RES-0402]  86.49 148.63 0 bottom
R400  10K  [SM-7351-RES-0402]  86.49 147.61 0 bottom
R401  10K  [SM-7351-RES-0402]  95.25 147.36 180 bottom
R402  0  [SM-7351-RES-0402]  78.36 100.03 0 top
R403  0  [SM-7351-RES-0402]  78.36 103.08 0 top
R404  0  [SM-7351-RES-0402]  78.36 104.09 0 top
R405  0  [SM-7351-RES-0402]  78.36 105.11 0 top
R406  0  [SM-7351-RES-0402]  78.36 101.05 0 top
R407  0  [SM-7351-RES-0402]  78.36 102.06 0 top
R408  470K  [SM-7351-RES-0402]  96.9 138.08 90 bottom
R409  0  [SM-7351-RES-0402]  78.36 99.01 0 top
R410  0  [SM-7351-RES-0402]  75.69 141.31 270 bottom
R411  0  [SM-7351-RES-0402]  74.55 141.31 270 bottom
R412  10K  [SM-7351-RES-0402]  77.22 147.66 0 top
R413  10  [SM-7351-RES-0402]  74.68 148.34 270 bottom
R414  47K  [SM-7351-RES-0402]  75.82 148.34 270 bottom
R415  2.0  [SM-7351-RES-0603]  76.96 145.16 90 bottom
R416  0  [SM-7351-RES-0402]  77.22 148.93 0 top
R417  10K  [SM-7351-RES-0402]  76.83 141.31 270 bottom
R418  0  [SM-7351-RES-0402]  56.61 88.29 0 bottom
R419  100K  [SM-7351-RES-0402]  154.36 103.47 270 bottom
R420  10K  [SM-7351-RES-0402]  56.61 87.23 180 bottom
R421  DNI  [SM-7351-RES-0402]  10.67 32 90 bottom
R422  4.7K  [SM-7351-RES-0402]  181.89 92.66 0 bottom
R423  4.7K  [SM-7351-RES-0402]  177.8 92.16 180 top
R424  1.62M  [SM-7351-RES-0402]  157.66 106.27 90 bottom
R425  10K  [SM-7351-RES-0402]  145.16 135.97 90 top
R426  22.1  [SM-7351-RES-0402]  124.08 73.74 180 top
R427  180K  [SM-7351-RES-0402]  157.66 104.11 90 bottom
R428  0  [SM-7351-RES-0402]  146.3 136.02 90 top
R429  100  [SM-7351-RES-0402]  187.1 91.14 270 bottom
R430  10K  [SM-7351-RES-0402]  144.02 135.97 90 top
R431  10K  [SM-7351-RES-0402]  142.75 125.18 0 bottom
R432  10K  [SM-7351-RES-0402]  142.24 121.75 0 bottom
R433  4.7K  [SM-7351-RES-0402]  182.02 95.2 0 bottom
R434  DNI  [SM-7351-RES-0402]  101.22 108.92 90 top
R435  18K  [SM-7351-RES-0402]  108.84 113.37 90 top
R436  18K  [SM-7351-RES-0402]  104.27 108.92 90 top
R437  DNI  [SM-7351-RES-0402]  106.81 113.37 90 top
R438  DNI  [SM-7351-RES-0402]  107.82 113.37 90 top
R439  DNI  [SM-7351-RES-0402]  103.25 108.92 90 top
R440  DNI  [SM-7351-RES-0402]  102.23 108.92 90 top
R441  DNI  [SM-7351-RES-0402]  110.87 113.37 90 top
R442  18K  [SM-7351-RES-0402]  109.86 113.37 90 top
R443  DNI  [SM-7351-RES-0402]  109.35 108.92 90 top
R444  DNI  [SM-7351-RES-0402]  110.36 108.92 90 top
R445  DNI  [SM-7351-RES-0402]  111.38 108.92 90 top
R446  DNI  [SM-7351-RES-0402]  112.39 108.92 90 top
R447  DNI  [SM-7351-RES-0402]  105.66 108.92 90 top
R448  DNI  [SM-7351-RES-0402]  113.41 108.92 90 top
R449  18K  [SM-7351-RES-0402]  106.68 108.92 90 top
R450  4.7K  [SM-7351-RES-0402]  186.59 88.47 180 bottom
R451  0  [SM-7351-RES-0402]  144.53 99.52 180 top
R453  10K  [SM-7351-RES-0402]  101.6 108.92 270 bottom
R454  DNI  [SM-7351-RES-0402]  108.84 113.37 270 bottom
R455  DNI  [SM-7351-RES-0402]  104.65 108.92 270 bottom
R456  10K  [SM-7351-RES-0402]  106.81 113.37 270 bottom
R457  10K  [SM-7351-RES-0402]  107.82 113.37 270 bottom
R458  10K  [SM-7351-RES-0402]  103.63 108.92 270 bottom
R459  10K  [SM-7351-RES-0402]  102.62 108.92 270 bottom
R460  10K  [SM-7351-RES-0402]  110.87 113.37 270 bottom
R461  DNI  [SM-7351-RES-0402]  109.86 113.37 270 bottom
R462  10K  [SM-7351-RES-0402]  109.35 108.92 270 bottom
R463  10K  [SM-7351-RES-0402]  110.36 108.92 270 bottom
R464  10K  [SM-7351-RES-0402]  111.38 108.92 270 bottom
R465  10K  [SM-7351-RES-0402]  112.39 108.92 270 bottom
R466  10K  [SM-7351-RES-0402]  105.66 108.92 270 bottom
R467  10K  [SM-7351-RES-0402]  113.41 108.92 270 bottom
